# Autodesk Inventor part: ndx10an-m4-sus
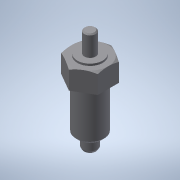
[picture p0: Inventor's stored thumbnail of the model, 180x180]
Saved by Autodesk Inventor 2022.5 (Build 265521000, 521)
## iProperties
Created: 2016-12
Part Number: ndx10an-m4-sus
Material: 一般
Document SubType Name: Modeling
Designer: imaocorp
Density: 1 g/cm^3
Appearance: 既定
Author: imaocorp
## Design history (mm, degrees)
node "ndx10an-m4-sus.x_t1"
node "ndx10an-m4-sus"
node "Base1"
